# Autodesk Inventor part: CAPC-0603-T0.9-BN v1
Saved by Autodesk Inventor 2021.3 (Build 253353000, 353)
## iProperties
Created: 2023-09
Part Number: CAPC-0603-T0.9-BN v1
Material: Generic
Document SubType Name: Modeling
Designer: AdminForWorker
Density: 1 g/cm^3
Appearance: Default
Title: CAPC-0603-T0.9-BN v1
Author: AdminForWorker
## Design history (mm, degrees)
feature "Body1"
body "Solid1"
